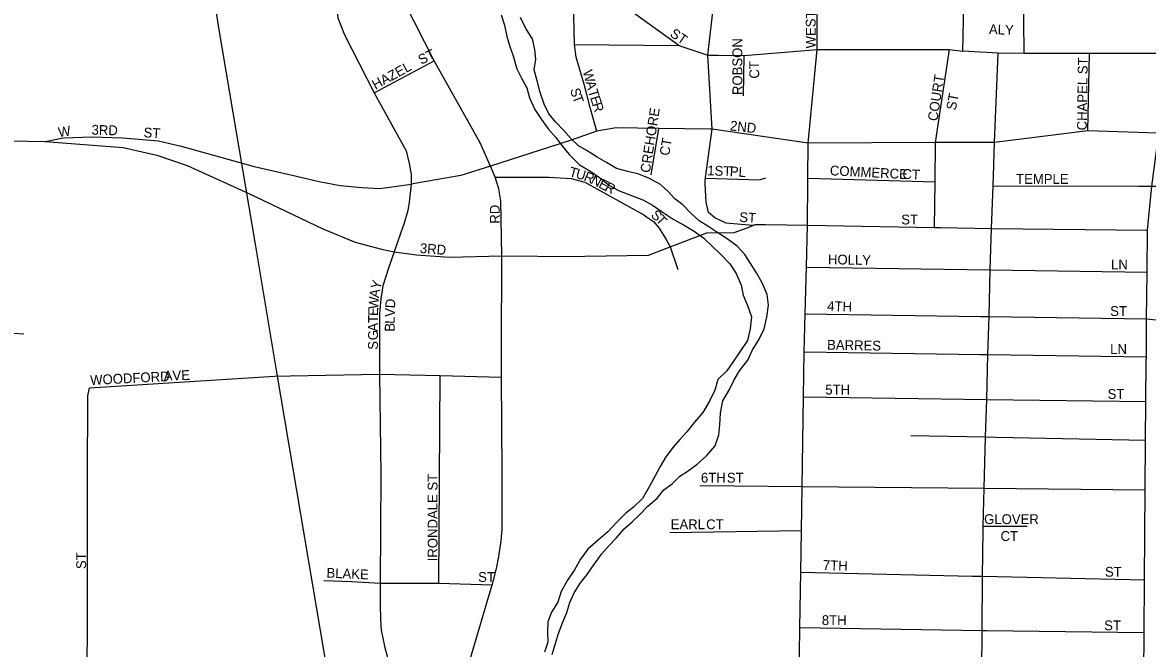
# Model space of a CAD drawing. Extents: x 1857828 to 2277390, y 930619 to 1324581.
# Drawn here: x 2071493 to 2077226, y 1224059 to 1227249 of the extents above; entities that cross this region are included whole.
import ezdxf

# ---------------------------------------------------------------- set-up
doc = ezdxf.new("R2010")
doc.units = 0
for name, color, linetype in [('GM_X_City_Street', 7, 'Continuous'), ('GM_X_City_Street_Text', 7, 'Continuous'), ('GM_X_Major_River', 7, 'Continuous'), ('GM_X_Minor_River', 7, 'Continuous'), ('GM_X_Rail_Line', 7, 'Continuous')]:
    doc.layers.add(name, color=color, linetype=linetype)

msp = doc.modelspace()

# ---------------------------------------------------------------- linework, layer by layer
at = {"layer": 'GM_X_City_Street'}
for points in [[(2074973.2, 1226459.1), (2075007.6, 1226705.5), (2074985, 1227082.6), (2075016.1, 1227346.4), (2075022.3, 1227564.5), (2075032, 1227877.7), (2075039.3, 1228153.7), (2075056.4, 1228188.8), (2075075.6, 1228209.3), (2075215.3, 1228356.1)], [(2074837.7, 1227131.7), (2074305.7, 1227515.5), (2074211.8, 1227580.7), (2073957.5, 1227757.2), (2073785.3, 1227878.4), (2073639.8, 1227953.5), (2073501.9, 1228009), (2073353.6, 1228062.8)], [(2073236.3, 1227794.8), (2073204.9, 1227752.8), (2073171.2, 1227636.8), (2073132.3, 1227547), (2073108, 1227479.2), (2073093.7, 1227409.2), (2073093.7, 1227335.8), (2073100.3, 1227272.3), (2073134.2, 1227185.7), (2073285.4, 1226891.1), (2073447.8, 1226595.3), (2073463.8, 1226531.2), (2073472.8, 1226475.1), (2073473.2, 1226424.8)], [(2073934.7, 1225579), (2073934.8, 1226060), (2073930.1, 1226339.6), (2073920.2, 1226400.8), (2073901, 1226460.5), (2073878, 1226517.3), (2073825.5, 1226636.6), (2073591.2, 1227054.5), (2073291.4, 1227642.6), (2073283.6, 1227734.4), (2073269.2, 1227752.8)], [(2075542, 1227112.1), (2075542.6, 1227345.4), (2075544.2, 1227547.8), (2075544.2, 1227549.9)], [(2076285.6, 1227103.6), (2076288.3, 1227263), (2076288.1, 1227329.7), (2076287.1, 1227365.4), (2076275.2, 1227383.2), (2076233.7, 1227418.8), (2076066.3, 1227542.4), (2076034.4, 1227565.6), (2075996, 1227603.2)], [(2074364.7, 1226896.3), (2074356.5, 1226928.2), (2074315, 1227071.8), (2074305.1, 1227137.8), (2074303.2, 1227283.2), (2074305.7, 1227515.5)], [(2076597.3, 1227091.9), (2076596.5, 1227258.8), (2076596.4, 1227361.9)], [(2074305.1, 1227137.8), (2074837.7, 1227131.7)], [(2074837.7, 1227131.7), (2074985, 1227082.6), (2074997.6, 1227082.5), (2075038, 1227082.3)], [(2075038, 1227082.3), (2075169.9, 1227081.7), (2075542, 1227112.1), (2076216.2, 1227112.1), (2076285.6, 1227103.6)], [(2075493, 1226216.7), (2075493, 1226216.7), (2075495, 1226439.9), (2075495.2, 1226456.3), (2075496.8, 1226635.1), (2075542, 1227112.1)], [(2076140.6, 1226205.3), (2076143.7, 1226437.1), (2076146.3, 1226637), (2076216.2, 1227112.1)], [(2077841.2, 1227083.5), (2077284.4, 1227091.2), (2076930.7, 1227091.5), (2076597.3, 1227091.9), (2076465.1, 1227092.4), (2076285.6, 1227103.6)], [(2076447, 1226637.9), (2076465.1, 1227092.4)], [(2076922.5, 1226696.6), (2076930.7, 1227091.5)], [(2073285.4, 1226891.1), (2073591.2, 1227054.5)], [(2075168, 1226874.9), (2075169.9, 1227081.7)], [(2074419.1, 1226694.6), (2074386.9, 1226809.1), (2074364.7, 1226896.3)], [(2067372.3, 1226699.7), (2067622.4, 1226632.9), (2067965.5, 1226480.6), (2068530.1, 1226180.3), (2068930, 1225982.1), (2069126.8, 1225924.1), (2069222.3, 1225910.8), (2069344.3, 1225909.6), (2069468.7, 1225922.9), (2069607.6, 1225950.7), (2069869.7, 1226019.5), (2070072.7, 1226083.5), (2070250.2, 1226163.2), (2070427.8, 1226259.9), (2070648.8, 1226402.4), (2070846.9, 1226525.6), (2070947.2, 1226575.2), (2071068, 1226618.6), (2071134.4, 1226631.9), (2071239.5, 1226648.8), (2071331.3, 1226651.3), (2071435.2, 1226646.4), (2071607.9, 1226642.8)], [(2075000.7, 1226705.6), (2074736, 1226709.1), (2074518.7, 1226712.1), (2074419.1, 1226694.6), (2074283.2, 1226648.3), (2073878, 1226517.3), (2073726, 1226468.9), (2073599.6, 1226446.8), (2073473.2, 1226424.8)], [(2074697.2, 1226472.6), (2074736, 1226709.1)], [(2075496.8, 1226635.1), (2075007.6, 1226705.5), (2075000.7, 1226705.6)], [(2077278, 1226685.7), (2076922.5, 1226696.6), (2076447, 1226637.9)], [(2071607.9, 1226642.8), (2071702.2, 1226660.9), (2071845.9, 1226667), (2072002.9, 1226662.1), (2072185.3, 1226646.4), (2072301.3, 1226619.8), (2072673.3, 1226516), (2072866.6, 1226471.3), (2073004.3, 1226438.7), (2073111.3, 1226419.2), (2073221.7, 1226409), (2073314.6, 1226403.6), (2073473.2, 1226424.8)], [(2071607.9, 1226642.8), (2072006.6, 1226612.2), (2072178.1, 1226572.7), (2072332.7, 1226520.8), (2072645.5, 1226377.1), (2073023.6, 1226198.3), (2073187.9, 1226129.4), (2073323, 1226094.6), (2073387.7, 1226080.6)], [(2076167.5, 1226637.1), (2076146.3, 1226637), (2075496.8, 1226635.1)], [(2076447, 1226637.9), (2076167.5, 1226637.1), (2076167.5, 1226637.1)], [(2076430.8, 1226200.1), (2076430.8, 1226200.1), (2076435.5, 1226329.7), (2076438.8, 1226417.1), (2076442.7, 1226522.7), (2076445.1, 1226586.7), (2076447, 1226637.9)], [(2077225.6, 1226190.9), (2077248.7, 1226415.5), (2077284, 1226685.5)], [(2073901, 1226460.5), (2074037.8, 1226460.8)], [(2074037.8, 1226460.8), (2074169.1, 1226461), (2074174.6, 1226460.8)], [(2074174.6, 1226460.8), (2074289.3, 1226454.9), (2074358.4, 1226435.5), (2074658.6, 1226268.7), (2074672.9, 1226259.2)], [(2075215.2, 1226214.6), (2075078.4, 1226227.2), (2075020.4, 1226253.1), (2074988.3, 1226281.1), (2074976.3, 1226333.3), (2074972.2, 1226427.5), (2074972.6, 1226448.2), (2074972.8, 1226455.6), (2074973.2, 1226459.1)], [(2074972.8, 1226455.6), (2075192.2, 1226449.9), (2075248.2, 1226447.9), (2075280.3, 1226458)], [(2073473.2, 1226424.8), (2073462.7, 1226332.8), (2073456.5, 1226291.3), (2073438, 1226226.1), (2073420.8, 1226179.6), (2073387.7, 1226080.6)], [(2075495.2, 1226456.3), (2076143.7, 1226437.1)], [(2076438.8, 1226417.1), (2077182.7, 1226415.6)], [(2077182.7, 1226415.6), (2077182.7, 1226415.6), (2077248.7, 1226415.5), (2077529.8, 1226414.9)], [(2074672.9, 1226259.2), (2074708.1, 1226235.5), (2074738.1, 1226200.7), (2074773, 1226143), (2074793.2, 1226105.9), (2074832.4, 1225991.2)], [(2074357.9, 1226057.9), (2074683, 1226064.1), (2074793.2, 1226105.9), (2074979.7, 1226177.5), (2075119.9, 1226179.4), (2075191.5, 1226204.8), (2075215.2, 1226214.6), (2075227.2, 1226219.5), (2075279.2, 1226220.5), (2075493, 1226216.7)], [(2075454.5, 1224144.2), (2075454.8, 1224166.7), (2075459.2, 1224447.4), (2075462.5, 1224660), (2075466, 1224884.3), (2075473.1, 1225341.7), (2075476.7, 1225570.3), (2075481.6, 1225764.6), (2075487.6, 1226003.2), (2075493, 1226216.7)], [(2075493, 1226216.7), (2076140.6, 1226205.3), (2076170.3, 1226204.7)], [(2076170.3, 1226204.7), (2076170.3, 1226204.7), (2076430.8, 1226200.1)], [(2076381.7, 1223944.1), (2076383.5, 1224150.7), (2076386, 1224427.1), (2076388, 1224657.8), (2076388.7, 1224683.3), (2076394, 1224875.8), (2076401.3, 1225137.1), (2076406.6, 1225328.8), (2076412.9, 1225557.3), (2076418.3, 1225750.7), (2076424.9, 1225989.1), (2076430.8, 1226200.1)], [(2076430.8, 1226200.1), (2077225.6, 1226190.9)], [(2077220, 1225523.7), (2077220.2, 1225546.1), (2077221.8, 1225738.7), (2077223.8, 1225977.2), (2077225.6, 1226190.9)], [(2073387.7, 1226080.6), (2073357.8, 1225996.6), (2073328.3, 1225906.7), (2073318.6, 1225840.5), (2073312.6, 1225764.7), (2073311.4, 1225456.7), (2073318.9, 1224943.8), (2073314.7, 1224392.7), (2073316.1, 1224283.8), (2073317.4, 1224205.7), (2073320.3, 1224152.7), (2073338.4, 1224071.7), (2073352.3, 1224013.1), (2073482.1, 1223778.7), (2073529.7, 1223691.9), (2073567.2, 1223528.9), (2073590.2, 1223382.6)], [(2073387.7, 1226080.6), (2073500.7, 1226065.3), (2073668.7, 1226053.3), (2073934.8, 1226060)], [(2073934.8, 1226060), (2074301.2, 1226056.8), (2074357.9, 1226057.9)], [(2075487.6, 1226003.2), (2076424.9, 1225989.1), (2077223.8, 1225977.2)], [(2075481.6, 1225764.6), (2076374.5, 1225751.3), (2076378.1, 1225751.3)], [(2076378.1, 1225751.3), (2076418.3, 1225750.7), (2077221.8, 1225738.7)], [(2077221.8, 1225738.7), (2077336.5, 1225727.2), (2077414.6, 1225719.6), (2077456.7, 1225715.9), (2077506.8, 1225710.2), (2077532.9, 1225700.3), (2077548.8, 1225692.5), (2077581.1, 1225676.5), (2077629.4, 1225638.7), (2077691.6, 1225599), (2077722, 1225580.1), (2077800.2, 1225531.4), (2078069.4, 1225376.6)], [(2073893.5, 1224407.5), (2073909.2, 1224466.9), (2073920.3, 1224528), (2073932.8, 1224607.6), (2073937, 1224667.6), (2073937, 1224953.6), (2073934.6, 1225441.1), (2073934.7, 1225579)], [(2075476.7, 1225570.3), (2076374.8, 1225557.8), (2076374.9, 1225557.8)], [(2076374.9, 1225557.8), (2076412.9, 1225557.3), (2077220.2, 1225546.1)], [(2077206.6, 1223930), (2077208.3, 1224140.5), (2077210.6, 1224409.2), (2077214.4, 1224868.4), (2077216.6, 1225121), (2077218.2, 1225317.5), (2077220, 1225523.7)], [(2071833.7, 1225386.8), (2072777.4, 1225446.9), (2072857.7, 1225448.4)], [(2072857.7, 1225448.4), (2073311.4, 1225456.7), (2073621.8, 1225450.7), (2073934.6, 1225441.1)], [(2073614.7, 1224392.7), (2073621.8, 1225450.7)], [(2071821.8, 1223210.7), (2071821.8, 1223211.9), (2071823.3, 1224925.6), (2071825.5, 1225346.7), (2071833.7, 1225386.8)], [(2075473.1, 1225341.7), (2076406.6, 1225328.8), (2077218.2, 1225317.5)], [(2076020.6, 1225144.7), (2076401.3, 1225137.1), (2076455.5, 1225136), (2076455.5, 1225136)], [(2076455.5, 1225136), (2077216.6, 1225121)], [(2074944.7, 1224889), (2075466, 1224884.3), (2076394, 1224875.8), (2077214.4, 1224868.4)], [(2076388.7, 1224683.3), (2076612.4, 1224682.7)], [(2074791.3, 1224651.1), (2075462.5, 1224660)], [(2073028.6, 1224405.2), (2073169.5, 1224401), (2073257.4, 1224396)], [(2073257.4, 1224396), (2073314.7, 1224392.7), (2073614.7, 1224392.7), (2073886.9, 1224382.9)], [(2073590.2, 1223382.6), (2073886.9, 1224382.9), (2073893.5, 1224407.5)], [(2075459.2, 1224447.4), (2076334.7, 1224428.3), (2076334.9, 1224428.3)], [(2076334.9, 1224428.3), (2076386, 1224427.1), (2077210.6, 1224409.2)], [(2075454.8, 1224166.7), (2076383.5, 1224150.7), (2076407.4, 1224150.3), (2077208.3, 1224140.5)], [(2075414.8, 1221605.1), (2075417.9, 1221804.7), (2075421.4, 1222029.7), (2075424.5, 1222223.6), (2075425.8, 1222305.7), (2075427.9, 1222442.2), (2075431.6, 1222680.5), (2075434.8, 1222887.4), (2075436.1, 1222969.7), (2075438, 1223091.8), (2075441, 1223281.7), (2075444.6, 1223515), (2075446.7, 1223649.2), (2075447.8, 1223715.4), (2075451.6, 1223960.1), (2075454.5, 1224144.2)]]:
    msp.add_lwpolyline(points, dxfattribs=at)
at = {"layer": 'GM_X_Major_River'}
for points in [[(2073933, 1227287.7), (2073949.3, 1227235.6), (2073961.5, 1227177.4), (2073975.8, 1227127.3), (2073994, 1227079.2), (2074012.4, 1227013), (2074036.6, 1226964.9), (2074062.9, 1226916.9), (2074077.1, 1226864.7), (2074103.5, 1226806.6), (2074137.8, 1226754.6), (2074172, 1226706.5), (2074210.3, 1226662.5), (2074240.6, 1226622.5), (2074278.9, 1226576.5), (2074331.2, 1226524.6), (2074383.5, 1226492.7), (2074433.7, 1226458.8), (2074484, 1226418.9), (2074530.2, 1226393), (2074596.5, 1226367.2), (2074654.8, 1226345.4), (2074703, 1226317.5), (2074747.2, 1226287.6), (2074809.5, 1226247.8), (2074861.8, 1226217.9), (2074910, 1226190), (2074964.3, 1226150.1), (2075010.6, 1226106.1), (2075048.9, 1226070.2), (2075097.2, 1226020.2), (2075129.5, 1225970.2), (2075155.8, 1225910.1), (2075166, 1225859.9), (2075188.3, 1225807.8), (2075208.6, 1225749.7), (2075200.9, 1225687.4), (2075187.1, 1225629.1), (2075149.2, 1225570.7), (2075113.4, 1225518.3), (2075081.5, 1225473.9), (2075035.6, 1225429.5), (2075021.8, 1225375.2), (2074993.9, 1225318.9), (2074960.1, 1225262.5), (2074918.2, 1225212.1), (2074878.3, 1225163.7), (2074842.4, 1225123.4), (2074808.5, 1225085.1), (2074770.6, 1225036.7), (2074742.7, 1224986.3), (2074714.9, 1224936), (2074687, 1224883.6), (2074653.2, 1224823.2), (2074607.3, 1224778.8), (2074567.3, 1224748.5), (2074521.4, 1224702.1), (2074475.5, 1224653.7), (2074427.6, 1224613.3), (2074373.6, 1224564.8), (2074335.8, 1224514.5), (2074305.9, 1224460.1), (2074270.1, 1224407.7), (2074238.2, 1224349.3), (2074220.4, 1224295), (2074188.6, 1224244.7), (2074170.7, 1224194.4), (2074168.9, 1224142.2), (2074169.2, 1224092), (2074153.3, 1224039.7)], [(2074191.5, 1224027.8), (2074207.3, 1224080.1), (2074223.1, 1224130.4), (2074244.9, 1224190.7), (2074266.7, 1224243), (2074282.6, 1224293.3), (2074304.4, 1224343.6), (2074336.3, 1224394), (2074370.2, 1224436.3), (2074404.1, 1224484.7), (2074443.9, 1224539.1), (2074481.8, 1224583.5), (2074517.7, 1224621.8), (2074559.6, 1224668.2), (2074599.6, 1224704.5), (2074637.5, 1224740.8), (2074677.4, 1224783.2), (2074729.4, 1224827.6), (2074761.3, 1224867.9), (2074803.3, 1224898.3), (2074843.2, 1224936.6), (2074885.2, 1224964.9), (2074931.1, 1224999.3), (2074979.1, 1225041.7), (2075023, 1225092.1), (2075040.8, 1225148.4), (2075046.6, 1225198.7), (2075050.3, 1225258.9), (2075062.1, 1225321.2), (2075095.9, 1225379.6), (2075119.8, 1225427.9), (2075147.6, 1225474.3), (2075189.5, 1225528.7), (2075213.3, 1225581), (2075245.2, 1225631.4), (2075273, 1225687.7), (2075286.8, 1225748), (2075294.6, 1225808.3), (2075288.3, 1225862.5), (2075262, 1225922.6), (2075233.7, 1225972.7), (2075201.4, 1226024.7), (2075173.2, 1226066.8), (2075134.9, 1226108.8), (2075084.6, 1226146.7), (2075036.4, 1226176.6), (2074990.1, 1226208.5), (2074941.9, 1226238.3), (2074899.6, 1226278.3), (2074857.3, 1226320.3), (2074817.1, 1226350.2), (2074782.9, 1226388.2), (2074744.6, 1226424.1), (2074688.4, 1226454), (2074634.1, 1226475.8), (2074578, 1226489.6), (2074519.7, 1226505.4), (2074469.5, 1226535.3), (2074421.3, 1226563.2), (2074371, 1226595.1), (2074326.8, 1226620.9), (2074288.5, 1226656.9), (2074250.3, 1226700.9), (2074210, 1226740.9), (2074175.7, 1226782.9), (2074151.5, 1226832.9), (2074131.2, 1226893.1), (2074114.9, 1226951.2), (2074100.6, 1227007.4), (2074108.4, 1227061.7), (2074104.2, 1227111.8), (2074091.9, 1227166), (2074057.6, 1227218.1), (2074031.3, 1227274.1)]]:
    msp.add_lwpolyline(points, dxfattribs=at)
at = {"layer": 'GM_X_Minor_River'}
msp.add_lwpolyline([(2071499.2, 1225661.3), (2071499.2, 1225661.3), (2071443.2, 1225663.5)], dxfattribs=at)
at = {"layer": 'GM_X_Rail_Line'}
msp.add_lwpolyline([(2073113, 1223547.6), (2072789.3, 1225467.5), (2072681.1, 1226110.1), (2072549.5, 1226891.1), (2072490.7, 1227243), (2072475.3, 1227351.1), (2072464.4, 1227437.9), (2072454.5, 1227529.3), (2072445.5, 1227627.4), (2072436.9, 1227781.6), (2072422.8, 1228048.9), (2072411.1, 1228279.5), (2072405, 1228383.1)], dxfattribs=at)

# ---------------------------------------------------------------- texts
at = {"layer": 'GM_X_City_Street_Text'}
for s, rotation, p in [('WEST AVE', 90, (2075534.9, 1227117.1)), ('ST', 325.29786, (2074788.4, 1227182.1)), ('ALY', 358.02611, (2076417.3, 1227190.2)), ('ROBSON', 90, (2075160.9, 1226879.5)), ('ST', 26.57754, (2073524.9, 1227033.1)), ('HAZEL', 28.81603, (2073291.4, 1226905.4)), ('CT', 90, (2075246.9, 1226963.1)), ('CHAPEL ST', 89.22321, (2076916.5, 1226699.2)), ('W', 284.67253, (2074347.8, 1227000.7)), ('COURT', 81.52837, (2076155.4, 1226744.5)), ('A', 285.04496, (2074362.4, 1226945)), ('S', 286.8196, (2074282.7, 1226906.7)), ('T', 289.94874, (2074293.8, 1226870.1)), ('T', 287.05816, (2074374.3, 1226900.7)), ('E', 287.69611, (2074384.8, 1226866.4)), ('ST', 79.38528, (2076248.8, 1226799.4)), ('R', 287.74647, (2074395.5, 1226832.9)), ('CREHORE', 81.2556, (2074690.2, 1226480.5)), ('2ND', 353.66247, (2075096.5, 1226699.7)), ('W', 8.77684, (2071678.7, 1226664.2)), ('3RD', 358.4097, (2071844.2, 1226677.7)), ('ST', 356.42537, (2072108.5, 1226664.5)), ('CT', 80.54161, (2074788.3, 1226567.7)), ('1ST', 357.51168, (2074981.5, 1226470.9)), ('PL', 356.42537, (2075096.1, 1226466.5)), ('COMMERCE', 357.1031, (2075606.4, 1226470.9)), ('T', 345.02283, (2074275, 1226466.2)), ('U', 344.24074, (2074308.9, 1226457.2)), ('R', 336.84604, (2074349.6, 1226445.8)), ('N', 332.95603, (2074385.2, 1226430.6)), ('CT', 356.82219, (2075976, 1226453.3)), ('TEMPLE', 0.00001, (2076556.3, 1226426.9)), ('E', 332.75056, (2074424.4, 1226410.6)), ('R', 332.70739, (2074455.7, 1226394.5)), ('RD', 90, (2073924.5, 1226223.9)), ('S', 318.47992, (2074691.7, 1226262.5)), ('T', 312.37289, (2074717, 1226240.2)), ('ST', 356.42537, (2075144.5, 1226233.3)), ('ST', 0.00001, (2075971.1, 1226220.1)), ('3RD', 355.58715, (2073516.6, 1226074.9)), ('HOLLY', 358.78182, (2075597.3, 1226017.7)), ('LN', 0.00001, (2077040.3, 1225991.3)), ('A', 82.28404, (2073309.2, 1225843.7)), ('Y', 75.05167, (2073314.7, 1225885.6)), ('W', 86.23066, (2073305.5, 1225787.5)), ('D', 86.82986, (2073391, 1225792)), ('4TH', 357.71044, (2075593.1, 1225780.1)), ('E', 87.86878, (2073304.2, 1225752.7)), ('V', 88.2729, (2073389.6, 1225748.3)), ('ST', 0.00001, (2077035.9, 1225753.7)), ('T', 89.86344, (2073304.1, 1225717.9)), ('A', 89.97034, (2073304.1, 1225673.9)), ('B', 89.95143, (2073389.2, 1225673.9)), ('L', 89.26196, (2073389.2, 1225713.4)), ('G', 89.97814, (2073304.1, 1225630)), ('S', 89.97268, (2073304.1, 1225581.5)), ('BARRES', 358.9316, (2075592.9, 1225582.2)), ('LN', 0.00001, (2077035.9, 1225560.1)), ('WOODFORD', 2.86077, (2071839, 1225401.7)), ('AVE', 1.9739, (2072213.2, 1225423.7)), ('5TH', 0.00001, (2075583.9, 1225353.3)), ('ST', 0.00001, (2077022.7, 1225331.3)), ('IRONDALE ST', 90, (2073607.7, 1224503.5)), ('6TH', 0.00001, (2074950.3, 1224904.5)), ('ST', 0.00001, (2075082.3, 1224904.5)), ('GLOVER', 0.00001, (2076393.5, 1224693.3)), ('EARL', 0.00001, (2074796.3, 1224667)), ('CT', 0.00001, (2074976.7, 1224667)), ('CT', 0.00001, (2076477.1, 1224607.3)), ('ST', 90, (2071816.9, 1224463.9)), ('7TH', 357.71079, (2075571.1, 1224460.1)), ('BLAKE', 357.50241, (2073041.1, 1224420.5)), ('ST', 0.00001, (2077009.5, 1224425)), ('ST', 0.00001, (2073815.1, 1224398.5)), ('8TH', 0.00001, (2075566.3, 1224178.6)), ('ST', 0.00001, (2077005.1, 1224152.1))]:
    msp.add_text(s, height=50, rotation=rotation, dxfattribs=at).set_placement(p)

doc.saveas('drawing.dxf')
